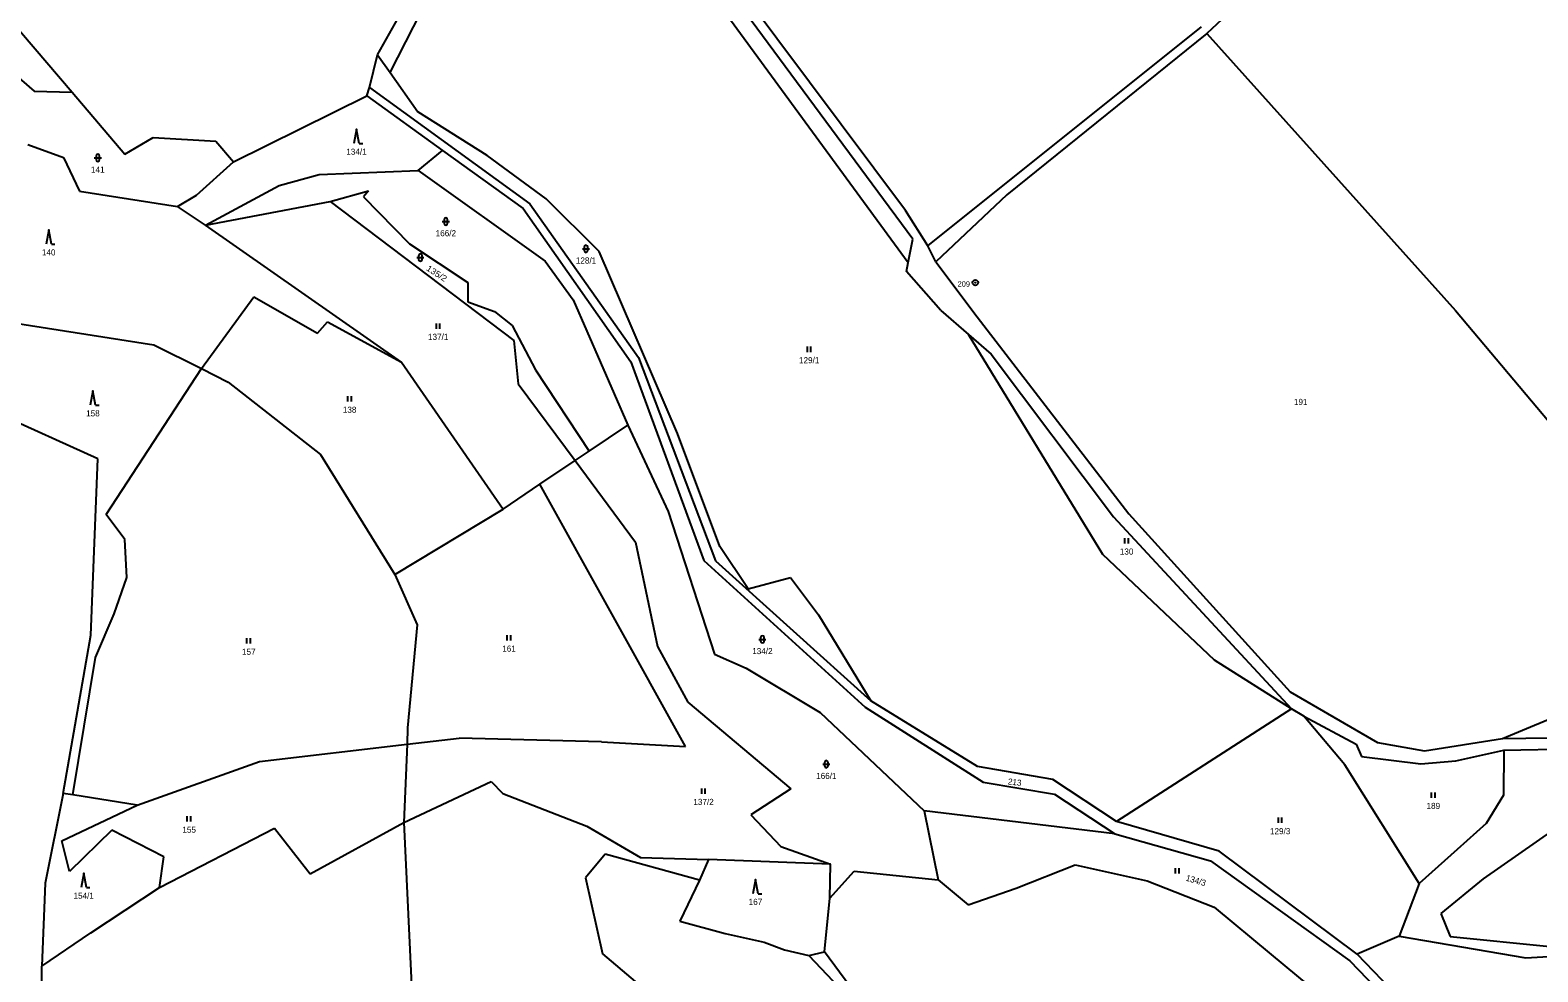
# Model space of a CAD drawing. Extents: x -601877 to -599786, y -1122905 to -1121218.
# Drawn here: x -600627.6 to -600206.4, y -1122435.1 to -1122172.1 of the extents above; entities that cross this region are included whole.
import ezdxf
from ezdxf.enums import TextEntityAlignment as Align

# ---------------------------------------------------------------- set-up
doc = ezdxf.new("R2010")
doc.units = 0
doc.header["$LTSCALE"] = 0.68
for name, color, linetype, lineweight in [('1', 7, 'Continuous', 25), ('3', 7, 'Continuous', 25), ('8', 7, 'Continuous', 25)]:
    doc.layers.add(name, color=color, linetype=linetype, lineweight=lineweight)
doc.layers.add('2', color=7, linetype='Continuous')

msp = doc.modelspace()

# ---------------------------------------------------------------- linework, layer by layer
at = {"layer": '1'}
for p, q in [((-600381.02, -1122230.51), (-600456.69, -1122128.15)), ((-600383.11, -1122222.48), (-600454.5, -1122127.05)), ((-600251.91, -1122129.15), (-600298.87, -1122173.08)), ((-600458.01, -1122133.71), (-600382.29, -1122237.02)), ((-600527.06, -1122183.95), (-600509.82, -1122150.16)), ((-600530.53, -1122179.04), (-600515.95, -1122153.01)), ((-600643.12, -1122157.6), (-600615.86, -1122189.5)), ((-600376.84, -1122232.39), (-600300.33, -1122171.21)), ((-600298.87, -1122173.08), (-600354.78, -1122218.11)), ((-600298.87, -1122173.08), (-600229.43, -1122250.39)), ((-600637.19, -1122179.91), (-600626.52, -1122189.15)), ((-600532.83, -1122188.16), (-600530.53, -1122179.04)), ((-600530.53, -1122179.04), (-600527.06, -1122183.95)), ((-600527.06, -1122183.95), (-600519.28, -1122194.96)), ((-600533.56, -1122190.53), (-600532.83, -1122188.16)), ((-600532.83, -1122188.16), (-600488.04, -1122220.6)), ((-600626.52, -1122189.15), (-600615.86, -1122189.5)), ((-600615.86, -1122189.5), (-600601.11, -1122206.76)), ((-600570.84, -1122208.95), (-600533.56, -1122190.53)), ((-600533.56, -1122190.53), (-600512.42, -1122205.75)), ((-600499.92, -1122207.18), (-600519.28, -1122194.96)), ((-600628.21, -1122204.06), (-600618.28, -1122207.69)), ((-600601.11, -1122206.76), (-600593.19, -1122202.14)), ((-600593.19, -1122202.14), (-600575.7, -1122203.13)), ((-600575.7, -1122203.13), (-600570.84, -1122208.95)), ((-600618.28, -1122207.69), (-600613.82, -1122217.15)), ((-600581.15, -1122218.27), (-600570.84, -1122208.95)), ((-600519.22, -1122211.33), (-600512.42, -1122205.75)), ((-600512.42, -1122205.75), (-600489.91, -1122221.95)), ((-600483.42, -1122219.28), (-600499.92, -1122207.18)), ((-600558.05, -1122215.51), (-600546.83, -1122212.43)), ((-600546.83, -1122212.43), (-600519.22, -1122211.33)), ((-600519.22, -1122211.33), (-600483.7, -1122236.65)), ((-600613.82, -1122217.15), (-600586.42, -1122221.39)), ((-600578.57, -1122226.63), (-600558.05, -1122215.51)), ((-600543.75, -1122220.03), (-600533.08, -1122217.05)), ((-600533.08, -1122217.05), (-600534.51, -1122218.71)), ((-600586.42, -1122221.39), (-600581.15, -1122218.27)), ((-600578.57, -1122226.63), (-600586.42, -1122221.39)), ((-600578.57, -1122226.63), (-600543.75, -1122220.03)), ((-600543.75, -1122220.03), (-600492.5, -1122258.77)), ((-600534.51, -1122218.71), (-600521.64, -1122231.8)), ((-600489.91, -1122221.95), (-600459.77, -1122264.77)), ((-600488.04, -1122220.6), (-600457.68, -1122263.53)), ((-600468.68, -1122233.92), (-600483.42, -1122219.28)), ((-600354.78, -1122218.11), (-600374.57, -1122236.85)), ((-600376.84, -1122232.39), (-600383.11, -1122222.48)), ((-600523.82, -1122264.84), (-600578.57, -1122226.63)), ((-600382.29, -1122237.02), (-600381.02, -1122230.51)), ((-600521.64, -1122231.8), (-600505.36, -1122242.59)), ((-600446.8, -1122284.77), (-600468.68, -1122233.92)), ((-600374.57, -1122236.85), (-600376.84, -1122232.39)), ((-600483.7, -1122236.65), (-600475.89, -1122247.43)), ((-600382.78, -1122239.54), (-600382.29, -1122237.02)), ((-600374.57, -1122236.85), (-600363.04, -1122252.16)), ((-600505.36, -1122242.59), (-600505.36, -1122247.98)), ((-600373.21, -1122250.43), (-600382.78, -1122239.54)), ((-600579.74, -1122266.66), (-600565.09, -1122246.66)), ((-600565.09, -1122246.66), (-600547.3, -1122256.75)), ((-600475.89, -1122247.43), (-600460.66, -1122282.44)), ((-600505.36, -1122247.98), (-600497.89, -1122250.73)), ((-600497.89, -1122250.73), (-600492.94, -1122254.59)), ((-600373.21, -1122250.43), (-600365.48, -1122257.14)), ((-600229.43, -1122250.39), (-600157.25, -1122336.33)), ((-600637.05, -1122253.13), (-600593.01, -1122260.01)), ((-600547.3, -1122256.75), (-600544.53, -1122253.64)), ((-600544.53, -1122253.64), (-600523.82, -1122264.84)), ((-600492.94, -1122254.59), (-600486.45, -1122267.02)), ((-600363.04, -1122252.16), (-600320.69, -1122307.2)), ((-600593.01, -1122260.01), (-600579.74, -1122266.66)), ((-600492.5, -1122258.77), (-600491.29, -1122270.88)), ((-600365.48, -1122257.14), (-600359.13, -1122262.65)), ((-600327.9, -1122318.56), (-600365.48, -1122257.14)), ((-600457.68, -1122263.53), (-600436.13, -1122320.32)), ((-600359.13, -1122262.65), (-600324.93, -1122308.1)), ((-600606.35, -1122307.41), (-600579.74, -1122266.66)), ((-600579.74, -1122266.66), (-600572.24, -1122270.44)), ((-600523.82, -1122264.84), (-600495.47, -1122305.88)), ((-600486.45, -1122267.02), (-600471.47, -1122289.71)), ((-600459.77, -1122264.77), (-600439.43, -1122320.24)), ((-600572.24, -1122270.44), (-600546.5, -1122290.69)), ((-600491.29, -1122270.88), (-600475.38, -1122292.35)), ((-600608.7, -1122291.84), (-600639.77, -1122277.8)), ((-600471.47, -1122289.71), (-600460.66, -1122282.44)), ((-600460.66, -1122282.44), (-600449.33, -1122306.59)), ((-600434.92, -1122316.36), (-600446.8, -1122284.77)), ((-600610.68, -1122341.15), (-600608.7, -1122291.84)), ((-600546.5, -1122290.69), (-600525.71, -1122324.15)), ((-600485.19, -1122298.95), (-600475.38, -1122292.35)), ((-600475.38, -1122292.35), (-600471.47, -1122289.71)), ((-600475.38, -1122292.35), (-600458.51, -1122315.12)), ((-600495.47, -1122305.88), (-600485.19, -1122298.95)), ((-600444.54, -1122372.24), (-600485.19, -1122298.95)), ((-600525.71, -1122324.15), (-600495.47, -1122305.88)), ((-600601.15, -1122314.41), (-600606.35, -1122307.41)), ((-600449.33, -1122306.59), (-600436.4, -1122346.38)), ((-600324.93, -1122308.1), (-600275.21, -1122361.71)), ((-600320.69, -1122307.2), (-600275.6, -1122356.94)), ((-600600.59, -1122324.96), (-600601.15, -1122314.41)), ((-600458.51, -1122315.12), (-600452.35, -1122344.29)), ((-600427, -1122328.19), (-600434.92, -1122316.36)), ((-600296.77, -1122348.06), (-600327.9, -1122318.56)), ((-600439.43, -1122320.24), (-600394.33, -1122361.18)), ((-600436.13, -1122320.32), (-600392.79, -1122359.42)), ((-600604.12, -1122335.12), (-600600.59, -1122324.96)), ((-600525.71, -1122324.15), (-600519.44, -1122338.23)), ((-600427, -1122328.19), (-600415.17, -1122325)), ((-600415.17, -1122325), (-600407.36, -1122335.4)), ((-600609.38, -1122347.34), (-600604.12, -1122335.12)), ((-600407.36, -1122335.4), (-600392.79, -1122359.42)), ((-600519.44, -1122338.23), (-600522.14, -1122367.02)), ((-600618.36, -1122385.34), (-600610.68, -1122341.15)), ((-600452.35, -1122344.29), (-600443.88, -1122359.81)), ((-600615.71, -1122385.72), (-600609.38, -1122347.34)), ((-600436.4, -1122346.38), (-600427.6, -1122350.34)), ((-600275.21, -1122361.71), (-600296.77, -1122348.06)), ((-600427.6, -1122350.34), (-600406.92, -1122362.67)), ((-600275.6, -1122356.94), (-600251.24, -1122371.06)), ((-600443.88, -1122359.81), (-600415.06, -1122384.02)), ((-600362.98, -1122377.8), (-600392.79, -1122359.42)), ((-600216.26, -1122369.96), (-600186.03, -1122357.27)), ((-600406.92, -1122362.67), (-600377.89, -1122390.18)), ((-600394.33, -1122361.18), (-600361.33, -1122382.2)), ((-600275.21, -1122361.71), (-600324.16, -1122393.1)), ((-600271.8, -1122363.69), (-600275.21, -1122361.71)), ((-600522.14, -1122367.02), (-600522.3, -1122371.58)), ((-600216.26, -1122369.96), (-600151.7, -1122368.97)), ((-600563.49, -1122376.37), (-600522.3, -1122371.58)), ((-600522.3, -1122371.58), (-600523.24, -1122393.43)), ((-600522.3, -1122371.58), (-600507.73, -1122369.88)), ((-600468.02, -1122370.87), (-600507.73, -1122369.88)), ((-600468.02, -1122370.87), (-600444.54, -1122372.24)), ((-600257.18, -1122371.5), (-600255.64, -1122375.02)), ((-600251.24, -1122371.06), (-600238.04, -1122373.37)), ((-600238.04, -1122373.37), (-600216.26, -1122369.96)), ((-600229.35, -1122376.23), (-600215.93, -1122373.26)), ((-600215.93, -1122373.26), (-600216.04, -1122385.81)), ((-600215.93, -1122373.26), (-600146.19, -1122371.89)), ((-600597.74, -1122388.56), (-600563.49, -1122376.37)), ((-600341.87, -1122381.43), (-600362.98, -1122377.8)), ((-600239.58, -1122410.46), (-600260.36, -1122377.33)), ((-600255.64, -1122375.02), (-600239.14, -1122377)), ((-600239.14, -1122377), (-600229.35, -1122376.23)), ((-600523.24, -1122393.43), (-600498.82, -1122381.98)), ((-600498.82, -1122381.98), (-600495.52, -1122385.29)), ((-600361.33, -1122382.2), (-600341.43, -1122385.51)), ((-600324.16, -1122393.1), (-600341.87, -1122381.43)), ((-600618.36, -1122385.34), (-600623.41, -1122410.39)), ((-600615.71, -1122385.72), (-600618.36, -1122385.34)), ((-600597.74, -1122388.56), (-600615.71, -1122385.72)), ((-600495.52, -1122385.29), (-600472.09, -1122394.42)), ((-600415.06, -1122384.02), (-600426.28, -1122391.28)), ((-600341.43, -1122385.51), (-600324.6, -1122396.62)), ((-600216.04, -1122385.81), (-600220.88, -1122393.73)), ((-600618.73, -1122398.55), (-600597.74, -1122388.56)), ((-600377.89, -1122390.18), (-600373.94, -1122409.45)), ((-600324.6, -1122396.62), (-600377.89, -1122390.18)), ((-600549.42, -1122407.74), (-600523.24, -1122393.43)), ((-600523.24, -1122393.43), (-600520.71, -1122446.81)), ((-600472.09, -1122394.42), (-600457.13, -1122403.23)), ((-600426.28, -1122391.28), (-600417.92, -1122400.09)), ((-600295.45, -1122401.47), (-600324.16, -1122393.1)), ((-600220.88, -1122393.73), (-600228.91, -1122401)), ((-600197.01, -1122391.97), (-600221.65, -1122409.14)), ((-600616.59, -1122407.1), (-600618.73, -1122398.55)), ((-600604.78, -1122395.54), (-600616.59, -1122407.1)), ((-600590.26, -1122402.97), (-600604.78, -1122395.54)), ((-600591.5, -1122411.6), (-600559.31, -1122394.97)), ((-600559.31, -1122394.97), (-600549.42, -1122407.74)), ((-600324.6, -1122396.62), (-600297.87, -1122404.11)), ((-600591.5, -1122411.6), (-600590.26, -1122402.97)), ((-600466.92, -1122402.24), (-600472.42, -1122408.84)), ((-600440.61, -1122409.51), (-600466.92, -1122402.24)), ((-600457.13, -1122403.23), (-600438.08, -1122403.75)), ((-600417.92, -1122400.09), (-600403.98, -1122405.06)), ((-600256.85, -1122430.19), (-600295.45, -1122401.47)), ((-600228.91, -1122401), (-600239.58, -1122410.46)), ((-600438.08, -1122403.75), (-600440.61, -1122409.51)), ((-600403.98, -1122405.06), (-600438.08, -1122403.75)), ((-600404.17, -1122414.57), (-600403.98, -1122405.06)), ((-600404.17, -1122414.57), (-600397.41, -1122407.03)), ((-600397.41, -1122407.03), (-600373.94, -1122409.45)), ((-600352.13, -1122411.72), (-600335.68, -1122405.25)), ((-600335.68, -1122405.25), (-600315.57, -1122409.68)), ((-600297.87, -1122404.11), (-600258.93, -1122432.06)), ((-600623.41, -1122410.39), (-600624.36, -1122433.54)), ((-600610.69, -1122424.23), (-600591.5, -1122411.6)), ((-600472.42, -1122408.84), (-600467.69, -1122430.08)), ((-600440.61, -1122409.51), (-600446.11, -1122421)), ((-600373.94, -1122409.45), (-600365.52, -1122416.45)), ((-600315.57, -1122409.68), (-600296.87, -1122417.09)), ((-600239.58, -1122410.46), (-600245.19, -1122425.21)), ((-600221.65, -1122409.14), (-600233.53, -1122418.83)), ((-600405.72, -1122429.56), (-600404.17, -1122414.57)), ((-600365.52, -1122416.45), (-600352.13, -1122411.72)), ((-600296.87, -1122417.09), (-600280.89, -1122430.24)), ((-600233.53, -1122418.83), (-600230.94, -1122425.27)), ((-600624.36, -1122433.54), (-600610.69, -1122424.23)), ((-600446.11, -1122421), (-600433.4, -1122424.4)), ((-600433.4, -1122424.4), (-600422.59, -1122426.8)), ((-600422.59, -1122426.8), (-600416.9, -1122428.98)), ((-600245.19, -1122425.21), (-600256.85, -1122430.19)), ((-600245.19, -1122425.21), (-600209.77, -1122431.26)), ((-600230.94, -1122425.27), (-600203.06, -1122428.07)), ((-600467.69, -1122430.08), (-600458.56, -1122437.79)), ((-600416.9, -1122428.98), (-600410.09, -1122430.52)), ((-600410.09, -1122430.52), (-600405.72, -1122429.56)), ((-600410.09, -1122430.52), (-600390.04, -1122451.6)), ((-600398.64, -1122439.15), (-600405.72, -1122429.56)), ((-600280.89, -1122430.24), (-600259.28, -1122448.16)), ((-600258.93, -1122432.06), (-600243.87, -1122447.69)), ((-600240.16, -1122447.58), (-600256.85, -1122430.19)), ((-600209.77, -1122431.26), (-600198.77, -1122430.6)), ((-600624.7, -1122525.05), (-600624.36, -1122433.54))]:
    msp.add_line(p, q, dxfattribs=at)
msp.add_lwpolyline([(-600260.36, -1122377.33), (-600271.8, -1122363.69), (-600257.18, -1122371.5)], dxfattribs=at)
at = {"layer": '3'}
for p, q in [((-600535.69, -1122203.82), (-600534.694, -1122203.82)), ((-600609.701, -1122207.801), (-600607.699, -1122207.801)), ((-600609.201, -1122207.301), (-600609.201, -1122208.302)), ((-600608.199, -1122208.302), (-600608.199, -1122207.301)), ((-600512.471, -1122225.571), (-600510.469, -1122225.571)), ((-600511.971, -1122225.071), (-600511.971, -1122226.072)), ((-600510.969, -1122226.072), (-600510.969, -1122225.071)), ((-600621.67, -1122231.93), (-600620.674, -1122231.93)), ((-600473.311, -1122233.191), (-600471.309, -1122233.191)), ((-600472.811, -1122232.691), (-600472.811, -1122233.692)), ((-600471.809, -1122233.692), (-600471.809, -1122232.691)), ((-600519.581, -1122235.651), (-600517.579, -1122235.651)), ((-600519.081, -1122235.151), (-600519.081, -1122236.152)), ((-600518.079, -1122236.152), (-600518.079, -1122235.151)), ((-600514.121, -1122255.52), (-600514.121, -1122254.02)), ((-600513.12, -1122255.52), (-600513.12, -1122254.02)), ((-600410.481, -1122262.03), (-600410.481, -1122260.53)), ((-600409.48, -1122262.03), (-600409.48, -1122260.53)), ((-600609.32, -1122276.87), (-600608.324, -1122276.87)), ((-600538.871, -1122275.88), (-600538.871, -1122274.38)), ((-600537.87, -1122275.88), (-600537.87, -1122274.38)), ((-600321.811, -1122315.48), (-600321.811, -1122313.98)), ((-600320.81, -1122315.48), (-600320.81, -1122313.98)), ((-600567.031, -1122343.46), (-600567.031, -1122341.96)), ((-600566.03, -1122343.46), (-600566.03, -1122341.96)), ((-600494.331, -1122342.58), (-600494.331, -1122341.08)), ((-600493.33, -1122342.58), (-600493.33, -1122341.08)), ((-600424.041, -1122342.271), (-600422.039, -1122342.271)), ((-600423.541, -1122341.771), (-600423.541, -1122342.772)), ((-600422.539, -1122342.772), (-600422.539, -1122341.771)), ((-600406.171, -1122377.131), (-600404.169, -1122377.131)), ((-600405.671, -1122376.631), (-600405.671, -1122377.632)), ((-600404.669, -1122377.632), (-600404.669, -1122376.631)), ((-600439.991, -1122385.39), (-600439.991, -1122383.89)), ((-600438.99, -1122385.39), (-600438.99, -1122383.89)), ((-600236.131, -1122386.52), (-600236.131, -1122385.02)), ((-600235.13, -1122386.52), (-600235.13, -1122385.02)), ((-600583.691, -1122393.15), (-600583.691, -1122391.65)), ((-600582.69, -1122393.15), (-600582.69, -1122391.65)), ((-600278.911, -1122393.56), (-600278.911, -1122392.06)), ((-600277.91, -1122393.56), (-600277.91, -1122392.06)), ((-600307.631, -1122407.71), (-600307.631, -1122406.21)), ((-600306.63, -1122407.71), (-600306.63, -1122406.21)), ((-600611.89, -1122411.6), (-600610.894, -1122411.6)), ((-600424.23, -1122413.3), (-600423.234, -1122413.3))]:
    msp.add_line(p, q, dxfattribs=at)
for points in [[(-600535.69, -1122203.82), (-600536.44, -1122199.82), (-600537.19, -1122203.82)], [(-600621.67, -1122231.93), (-600622.42, -1122227.93), (-600623.17, -1122231.93)], [(-600609.32, -1122276.87), (-600610.07, -1122272.87), (-600610.82, -1122276.87)], [(-600611.89, -1122411.6), (-600612.64, -1122407.6), (-600613.39, -1122411.6)], [(-600424.23, -1122413.3), (-600424.98, -1122409.3), (-600425.73, -1122413.3)]]:
    msp.add_lwpolyline(points, dxfattribs=at)
for centre, start, end in [((-600608.7, -1122207.3009), 0, 180), ((-600608.7, -1122208.3009), 180, 359.98789), ((-600511.47, -1122225.0709), 0, 180), ((-600511.47, -1122226.0709), 180, 359.98789), ((-600518.58, -1122235.1509), 0, 180), ((-600472.31, -1122232.6909), 0, 180), ((-600472.31, -1122233.6909), 180, 359.98789), ((-600518.58, -1122236.1509), 180, 359.98789), ((-600423.04, -1122341.7709), 0, 180), ((-600423.04, -1122342.7709), 180, 359.98789), ((-600405.17, -1122376.6309), 0, 180), ((-600405.17, -1122377.6309), 180, 359.98789)]:
    msp.add_arc(centre, 0.5, start, end, dxfattribs=at)
at = {"layer": '8'}
for radius in [0.75, 0.03]:
    msp.add_circle((-600363.56, -1122242.6598), radius, dxfattribs=at)

# ---------------------------------------------------------------- texts
at = {"layer": '2'}
for s, p in [('134/1', (-600536.44, -1122206.945)), ('141', (-600608.699, -1122211.925)), ('166/2', (-600511.47, -1122229.695)), ('140', (-600622.419, -1122235.055)), ('128/1', (-600472.31, -1122237.315)), ('137/1', (-600513.61, -1122258.645)), ('129/1', (-600409.97, -1122265.155)), ('191', (-600272.659, -1122276.805)), ('158', (-600610.069, -1122279.995)), ('138', (-600538.359, -1122279.005)), ('130', (-600321.299, -1122318.605)), ('161', (-600493.819, -1122345.705)), ('157', (-600566.519, -1122346.585)), ('134/2', (-600423.04, -1122346.395)), ('166/1', (-600405.17, -1122381.255)), ('137/2', (-600439.48, -1122388.515)), ('189', (-600235.619, -1122389.645)), ('155', (-600583.179, -1122396.275)), ('129/3', (-600278.4, -1122396.685)), ('154/1', (-600612.64, -1122414.725)), ('167', (-600424.979, -1122416.425))]:
    msp.add_text(s, height=1.7, dxfattribs=at).set_placement(p, align=Align.CENTER)
at = {"layer": '2', "width": 1.1}
msp.add_text('135/2', height=1.7, rotation=327, dxfattribs=at).set_placement((-600514.4859, -1122240.7886), align=Align.CENTER)
at = {"layer": '2'}
for s, rotation, p in [('213', 353, (-600352.6481, -1122382.998)), ('134/3', 344, (-600302.1678, -1122410.4219))]:
    msp.add_text(s, height=1.7, rotation=rotation, dxfattribs=at).set_placement(p, align=Align.CENTER)
at = {"layer": '8'}
msp.add_text('209', height=1.5, dxfattribs=at).set_placement((-600365.059, -1122243.777), align=Align.RIGHT)

doc.saveas('drawing.dxf')
